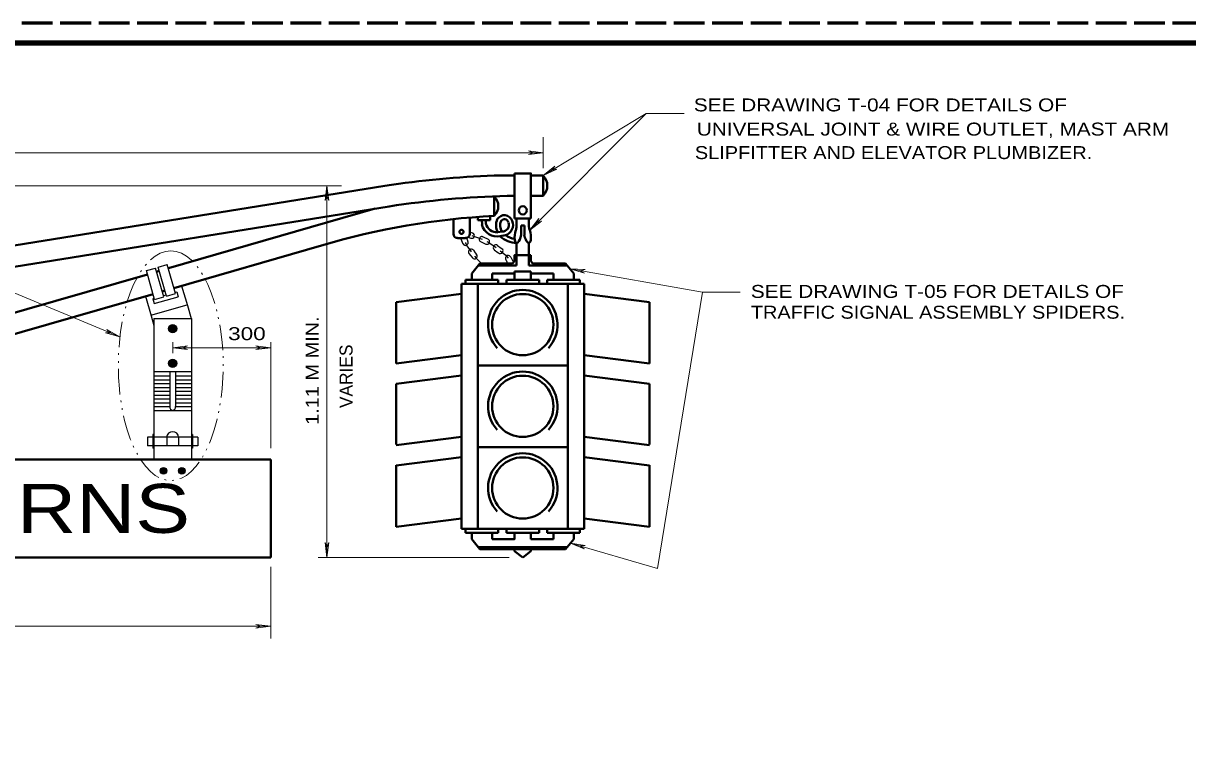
# Model space of a CAD drawing. Extents: x 312583 to 312853, y 144419 to 144586.
# Drawn here: x 312733 to 312801.3, y 144544.1 to 144586.2 of the extents above; entities that cross this region are included whole.
import ezdxf
from ezdxf.enums import TextEntityAlignment as Align

# ---------------------------------------------------------------- set-up
doc = ezdxf.new("R2010")
doc.units = 0
doc.header["$LTSCALE"] = 0.3
doc.linetypes.add('DASH_DOUBLE_DOT', pattern=[9.2, 5, -1.2, 0.3, -1.2, 0.3, -1.2])
doc.linetypes.add('LONG_DASHED', pattern=[7.5, 6, -1.5])
for name, color, linetype, lineweight in [('1', 7, 'Continuous', 40), ('2', 7, 'Continuous', 13), ('63', 7, 'LONG_DASHED', 60)]:
    doc.layers.add(name, color=color, linetype=linetype, lineweight=lineweight)

msp = doc.modelspace()

# ---------------------------------------------------------------- hatches: boundary and pattern name
at = {"layer": '1'}
for points in [[(312742.0334, 144568.3054, 1), (312741.5514, 144568.3054, 1)], [(312741.9621, 144568.3054, 1), (312741.6227, 144568.3054, 1)], [(312742.0308, 144566.2761, 1), (312741.5488, 144566.2761, 1)], [(312741.9595, 144566.2761, 1), (312741.6201, 144566.2761, 1)], [(312741.4415, 144559.9738, 1), (312741.0592, 144559.9738, 1)], [(312742.5203, 144559.9738, 1), (312742.138, 144559.9738, 1)]]:
    msp.add_hatch(color=256, dxfattribs=at).paths.add_polyline_path(points)

# ---------------------------------------------------------------- linework, layer by layer
for p, q in [((312761.8484, 144577.2983), (312760.6524, 144577.2983)), ((312761.8484, 144574.7759), (312761.8484, 144577.4133)), ((312763.5274, 144577.2983), (312762.8068, 144577.2983)), ((312763.5274, 144577.2983), (312763.5274, 144576.1253)), ((312699.5568, 144567.8759), (312754.2354, 144576.6849)), ((312760.6524, 144576.0716), (312760.6524, 144574.9216)), ((312761.8484, 144576.1023), (312761.4191, 144576.1023)), ((312763.5274, 144576.1023), (312762.8068, 144576.1023)), ((312699.5568, 144566.6493), (312754.4884, 144575.4813)), ((312741.5366, 144571.8488), (312753.6758, 144575.3509)), ((312758.2604, 144574.7376), (312758.2604, 144573.8713)), ((312759.2188, 144574.8296), (312759.2188, 144573.8713)), ((312759.6941, 144574.8679), (312759.6941, 144574.6686)), ((312760.4148, 144574.6686), (312759.6941, 144574.6686)), ((312759.9318, 144574.6686), (312759.9394, 144574.4156)), ((312760.1694, 144574.6686), (312760.1694, 144574.4769)), ((312760.4148, 144574.9139), (312760.4148, 144574.6686)), ((312762.8068, 144574.7759), (312761.8484, 144574.7759)), ((312761.9711, 144574.2853), (312761.9711, 144574.7759)), ((312762.6918, 144574.2853), (312762.6918, 144574.7759)), ((312762.6918, 144574.2853), (312762.6918, 144574.7759)), ((312761.1201, 144574.0016), (312760.8594, 144573.9633)), ((312761.0128, 144573.7409), (312761.3118, 144573.7946)), ((312762.4234, 144574.3696), (312762.2394, 144574.3696)), ((312762.2394, 144573.8099), (312762.2394, 144574.3696)), ((312762.4234, 144573.8099), (312762.4234, 144574.3696)), ((312741.8649, 144570.6936), (312750.5248, 144573.1966)), ((312758.9734, 144573.6259), (312758.4981, 144573.6259)), ((312761.9711, 144572.6216), (312761.9711, 144573.3346)), ((312762.6918, 144572.6216), (312762.6918, 144573.3499)), ((312761.8484, 144572.2613), (312761.8484, 144572.6216)), ((312761.9711, 144572.0236), (312761.9711, 144572.6216)), ((312762.6918, 144572.0236), (312762.6918, 144572.6216)), ((312762.8068, 144572.2613), (312762.8068, 144572.6216)), ((312759.8168, 144572.1386), (312759.3338, 144571.5406)), ((312759.7171, 144572.0236), (312761.9711, 144572.0236)), ((312761.7334, 144572.1386), (312759.8168, 144572.1386)), ((312761.8484, 144572.2613), (312761.7334, 144572.1386)), ((312762.6918, 144572.0236), (312764.9381, 144572.0236)), ((312762.8068, 144572.2613), (312762.9294, 144572.1386)), ((312764.8461, 144572.1386), (312762.9294, 144572.1386)), ((312764.8461, 144572.1386), (312765.3214, 144571.5406)), ((312718.5807, 144565.2268), (312740.3144, 144571.4967)), ((312740.8436, 144571.6493), (312740.9991, 144571.6942)), ((312760.8901, 144571.1803), (312758.9734, 144571.1803)), ((312758.9734, 144570.9426), (312758.9734, 144571.1803)), ((312759.3338, 144571.1803), (312759.3338, 144571.5406)), ((312761.8484, 144571.5406), (312760.5298, 144571.5406)), ((312760.5298, 144571.1803), (312760.5298, 144571.5406)), ((312760.8901, 144570.9426), (312760.8901, 144571.1803)), ((312763.2898, 144571.1803), (312761.3731, 144571.1803)), ((312761.3731, 144570.9426), (312761.3731, 144571.1803)), ((312762.8068, 144571.6633), (312761.8484, 144571.6633)), ((312761.8484, 144571.1803), (312761.8484, 144571.6633)), ((312762.8068, 144571.1803), (312762.8068, 144571.6633)), ((312762.8068, 144571.5406), (312764.1254, 144571.5406)), ((312763.2898, 144570.9426), (312763.2898, 144571.1803)), ((312763.7651, 144571.1803), (312765.6818, 144571.1803)), ((312763.7651, 144570.9426), (312763.7651, 144571.1803)), ((312764.1254, 144571.1803), (312764.1254, 144571.5406)), ((312765.3214, 144571.1803), (312765.3214, 144571.5406)), ((312765.6818, 144570.9426), (312765.6818, 144571.1803)), ((312741.1852, 144570.4982), (312741.329, 144570.5397)), ((312765.9271, 144570.9426), (312758.7358, 144570.9426)), ((312758.7358, 144556.5676), (312758.7358, 144570.9426)), ((312759.6941, 144556.5676), (312759.6941, 144570.9426)), ((312764.9688, 144556.5676), (312764.9688, 144570.9426)), ((312765.9271, 144556.5676), (312765.9271, 144570.9426)), ((312718.9106, 144564.0723), (312740.6426, 144570.3417)), ((312758.7358, 144570.3446), (312754.9024, 144569.8616)), ((312754.9024, 144566.2736), (312754.9024, 144569.8616)), ((312765.9271, 144570.3446), (312769.7604, 144569.8616)), ((312769.7604, 144566.2736), (312769.7604, 144569.8616)), ((312758.7358, 144566.7489), (312754.9024, 144566.2736)), ((312765.9271, 144566.7489), (312769.7604, 144566.2736)), ((312759.6941, 144566.1509), (312764.9688, 144566.1509)), ((312758.7358, 144565.5529), (312754.9024, 144565.0699)), ((312754.9024, 144561.5049), (312754.9024, 144565.0699)), ((312765.9271, 144565.5529), (312769.7604, 144565.0699)), ((312769.7604, 144561.5049), (312769.7604, 144565.0699)), ((312758.7358, 144561.9573), (312754.9024, 144561.4819)), ((312765.9271, 144561.9573), (312769.7604, 144561.4819)), ((312759.6941, 144561.3593), (312764.9688, 144561.3593)), ((312747.5424, 144560.6386), (312712.9734, 144560.6386)), ((312747.5424, 144560.6386), (312747.5424, 144554.8886)), ((312758.7358, 144560.7613), (312754.9024, 144560.2783)), ((312754.9024, 144556.6903), (312754.9024, 144560.3089)), ((312765.9271, 144560.7613), (312769.7604, 144560.2783)), ((312769.7604, 144556.6903), (312769.7604, 144560.3089)), ((312758.7358, 144557.1656), (312754.9024, 144556.6903)), ((312765.9271, 144557.1656), (312769.7604, 144556.6903)), ((312765.9271, 144556.5676), (312758.7358, 144556.5676)), ((312758.9734, 144556.5676), (312758.9734, 144556.3299)), ((312760.8901, 144556.3299), (312758.9734, 144556.3299)), ((312759.3338, 144556.3299), (312759.3338, 144555.9696)), ((312760.5298, 144556.3299), (312760.5298, 144555.9696)), ((312760.8901, 144556.5676), (312760.8901, 144556.3299)), ((312761.3731, 144556.5676), (312761.3731, 144556.3299)), ((312763.2898, 144556.3299), (312761.3731, 144556.3299)), ((312762.8068, 144556.3299), (312762.8068, 144555.9696)), ((312763.2898, 144556.5676), (312763.2898, 144556.3299)), ((312763.7651, 144556.5676), (312763.7651, 144556.3299)), ((312763.7651, 144556.3299), (312765.6818, 144556.3299)), ((312764.1254, 144556.3299), (312764.1254, 144555.9696)), ((312765.3214, 144556.3299), (312765.3214, 144555.9696)), ((312765.6818, 144556.5676), (312765.6818, 144556.3299)), ((312759.8168, 144555.3716), (312759.3338, 144555.9696)), ((312759.7171, 144555.4866), (312764.9381, 144555.4866)), ((312764.8461, 144555.3716), (312759.8168, 144555.3716)), ((312761.8484, 144555.3716), (312761.8484, 144555.2489)), ((312762.8068, 144555.9696), (312764.1254, 144555.9696)), ((312762.8068, 144555.3716), (312762.8068, 144555.2489)), ((312764.8461, 144555.3716), (312765.3214, 144555.9696)), ((312747.5424, 144554.8886), (312712.9734, 144554.8886)), ((312762.3314, 144554.8886), (312761.8484, 144555.2489)), ((312762.3314, 144554.8886), (312762.8068, 144555.2489))]:
    msp.add_line(p, q, dxfattribs=at)
at = {"layer": '1', "lineweight": 25}
for p, q in [((312759.2188, 144573.9863), (312759.3951, 144573.9173)), ((312759.0194, 144573.6336), (312759.1114, 144573.4189)), ((312759.1191, 144573.6796), (312759.2801, 144573.6183)), ((312759.3338, 144573.7716), (312759.9394, 144573.5569)), ((312740.2528, 144571.7134), (312740.7806, 144571.8616)), ((312741.2807, 144570.1762), (312740.7806, 144571.8616)), ((312740.938, 144571.9079), (312741.4751, 144572.0653)), ((312741.4196, 144570.2225), (312740.938, 144571.9079)), ((312741.9567, 144570.3706), (312741.4751, 144572.0653)), ((312740.7343, 144570.0188), (312740.2528, 144571.7134)), ((312741.4196, 144570.2225), (312741.9567, 144570.3706)), ((312741.9356, 144570.4449), (312742.0308, 144570.4725)), ((312742.0308, 144570.4725), (312742.1141, 144570.1854)), ((312742.3178, 144570.8245), (312742.6512, 144569.6669)), ((312740.1972, 144570.2132), (312740.5306, 144569.0557)), ((312740.5162, 144569.1056), (312742.6368, 144569.7168)), ((312740.6256, 144570.0658), (312740.7137, 144570.0913)), ((312740.6256, 144570.0658), (312740.7065, 144569.778)), ((312740.7065, 144569.778), (312742.1141, 144570.1854)), ((312740.7343, 144570.0188), (312741.2807, 144570.1762)), ((312741.2591, 144570.2491), (312741.4003, 144570.29)), ((312740.5306, 144569.0557), (312740.695, 144568.492)), ((312742.6512, 144569.6669), (312742.8666, 144568.9128)), ((312740.695, 144568.9128), (312742.8897, 144568.9128)), ((312740.695, 144568.9128), (312740.695, 144560.6386)), ((312742.8897, 144568.9128), (312742.8897, 144560.6386)), ((312740.695, 144565.7966), (312742.8897, 144565.7966)), ((312741.621, 144565.7966), (312741.621, 144563.7408)), ((312741.9544, 144565.7966), (312741.9544, 144563.7408)), ((312740.695, 144565.5373), (312741.621, 144565.5373)), ((312740.695, 144565.3151), (312741.621, 144565.3151)), ((312740.695, 144565.0928), (312741.621, 144565.0928)), ((312741.9544, 144565.5373), (312742.8897, 144565.5373)), ((312741.9544, 144565.3151), (312742.8897, 144565.3151)), ((312741.9544, 144565.0928), (312742.8897, 144565.0928)), ((312740.695, 144564.8613), (312741.621, 144564.8613)), ((312740.695, 144564.6391), (312741.621, 144564.6391)), ((312740.695, 144564.4168), (312741.621, 144564.4168)), ((312741.9544, 144564.8613), (312742.8897, 144564.8613)), ((312741.9544, 144564.6391), (312742.8897, 144564.6391)), ((312741.9544, 144564.4168), (312742.8897, 144564.4168)), ((312740.695, 144564.1853), (312741.621, 144564.1853)), ((312740.695, 144563.9631), (312741.621, 144563.9631)), ((312740.695, 144563.7408), (312741.621, 144563.7408)), ((312741.9544, 144564.1853), (312742.8897, 144564.1853)), ((312741.9544, 144563.9631), (312742.8897, 144563.9631)), ((312741.9544, 144563.7408), (312742.8897, 144563.7408)), ((312740.695, 144563.5093), (312742.8897, 144563.5093)), ((312740.3153, 144561.9351), (312740.3153, 144561.4443)), ((312740.6209, 144561.9351), (312740.3153, 144561.9351)), ((312740.6209, 144562.0925), (312740.6209, 144561.2961)), ((312740.695, 144562.0925), (312740.6209, 144562.0925)), ((312742.8897, 144561.9351), (312740.695, 144561.9351)), ((312741.4451, 144561.9351), (312741.4451, 144561.4443)), ((312742.1396, 144561.9351), (312742.1396, 144561.4443)), ((312742.9638, 144562.0925), (312742.8897, 144562.0925)), ((312742.9638, 144562.0925), (312742.9638, 144561.2961)), ((312743.2694, 144561.9351), (312742.9638, 144561.9351)), ((312743.2694, 144561.9351), (312743.2694, 144561.4443)), ((312740.6209, 144561.4443), (312740.3153, 144561.4443)), ((312740.695, 144561.2961), (312740.6209, 144561.2961)), ((312742.8897, 144561.4443), (312740.695, 144561.4443)), ((312742.9638, 144561.2961), (312742.8897, 144561.2961)), ((312743.2694, 144561.4443), (312742.9638, 144561.4443))]:
    msp.add_line(p, q, dxfattribs=at)
at = {"layer": '1', "lineweight": 158}
msp.add_lwpolyline([(312616.5, 144423.1446), (312616.5, 144585.0846), (312849, 144585.0846)], dxfattribs=at)
at = {"layer": '1'}
for points in [[(312762.8068, 144574.7759), (312762.8068, 144577.4133), (312761.8484, 144577.4133)], [(312762.8068, 144572.6216), (312761.8484, 144572.6216), (312762.8068, 144572.6216)], [(312761.8484, 144556.3299), (312761.8484, 144555.9696), (312760.5298, 144555.9696)]]:
    msp.add_lwpolyline(points, dxfattribs=at)
at = {"layer": '1', "lineweight": 25}
for points in [[(312758.6898, 144573.6029), (312758.6974, 144573.5876), (312758.8201, 144573.2809)], [(312758.9658, 144573.3576), (312758.9734, 144573.3346), (312759.0961, 144573.1123), (312759.2341, 144572.9053), (312759.3031, 144572.8133)], [(312759.8858, 144573.4036), (312759.8934, 144573.3959), (312760.1618, 144573.2733)], [(312759.9931, 144573.7026), (312760.0161, 144573.6949), (312760.2921, 144573.5646)], [(312760.2308, 144573.4189), (312760.4071, 144573.3346), (312760.7598, 144573.0663)], [(312760.8518, 144573.1966), (312761.0664, 144573.0356), (312761.1124, 144572.9973)], [(312759.1728, 144572.7213), (312759.2801, 144572.5756), (312759.3721, 144572.4606)], [(312759.4334, 144572.9053), (312759.5331, 144572.7673), (312759.6174, 144572.6599)], [(312759.4948, 144572.5603), (312759.5944, 144572.4453), (312759.6864, 144572.3456), (312759.8398, 144572.2153), (312759.9471, 144572.1386)], [(312760.6601, 144572.9436), (312760.8748, 144572.7826), (312760.9131, 144572.7519)], [(312761.0128, 144572.8746), (312761.3271, 144572.6293), (312761.4728, 144572.4376)], [(312761.5954, 144572.5373), (312761.6261, 144572.4989), (312761.7794, 144572.1846)], [(312761.3424, 144572.3379), (312761.3501, 144572.3303), (312761.4421, 144572.1386)]]:
    msp.add_lwpolyline(points, dxfattribs=at)
at = {"layer": '1'}
for centre, radius in [((312762.33, 144575.2541), 0.2396), ((312758.7362, 144573.9882), 0.1198), ((312762.33, 144568.5458), 1.7969), ((312762.33, 144563.7541), 1.7969), ((312762.33, 144558.9625), 1.7969)]:
    msp.add_circle(centre, radius, dxfattribs=at)
at = {"layer": '1', "lineweight": 25}
for centre, radius in [((312741.7924, 144568.3054), 0.241), ((312741.7924, 144568.3054), 0.1697), ((312741.7898, 144566.2761), 0.241), ((312741.7898, 144566.2761), 0.1697), ((312741.2504, 144559.9738), 0.1911), ((312742.3292, 144559.9738), 0.1911)]:
    msp.add_circle(centre, radius, dxfattribs=at)
at = {"layer": '1'}
for centre, radius, start, end in [((312762.9252, 144519.8457), 57.5, 92.26498, 98.69127), ((312762.8978, 144576.7012), 0.8697, 316.42875, 43.57125), ((312762.9271, 144520.2995), 55.8229, 91.54908, 98.69123), ((312760.0869, 144575.4968), 0.806, 314.6086, 45.3914), ((312762.8277, 144531.6439), 43.3337, 92.87671, 106.4991), ((312760.8237, 144574.6332), 0.6743, 193.64871, 273.00151), ((312761.6827, 144574.371), 0.9206, 157.02326, 206.52483), ((312761.2509, 144574.4861), 0.4824, 17.33553, 149.56479), ((312761.6827, 144574.371), 0.6811, 157.00611, 212.48195), ((312761.2509, 144574.4861), 0.2428, 17.33553, 149.56479), ((312761.1286, 144574.3938), 0.3891, 268.34899, 22.04299), ((312761.1286, 144574.3938), 0.6287, 286.80498, 22.04299), ((312758.4967, 144573.8684), 0.2396, 180, 270), ((312758.9758, 144573.8684), 0.2396, 270, 0), ((312760.8237, 144574.6332), 0.9138, 193.64871, 281.97007), ((312761.9269, 144574.5949), 1.0122, 232.48654, 265.6903), ((312760.9745, 144574.4162), 1.0043, 340.68381, 352.70057), ((312763.6855, 144574.4162), 1.0043, 187.29943, 199.31619), ((312761.9269, 144574.5949), 1.2518, 223.12306, 271.78295), ((312762.33, 144568.5458), 2.0365, 317.48872, 222.69673), ((312762.33, 144563.7541), 2.0365, 317.48872, 222.69673), ((312762.33, 144558.9625), 2.0365, 317.48872, 222.69673)]:
    msp.add_arc(centre, radius, start, end, dxfattribs=at)
at = {"layer": '1', "lineweight": 25}
for centre, radius, start, end in [((312759.3369, 144573.7706), 0.1597, 250.0911, 70.0911), ((312758.8419, 144573.6516), 0.1597, 188.19055, 198.42777), ((312758.9635, 144573.356), 0.1597, 209.38072, 29.38072), ((312759.9376, 144573.5531), 0.1597, 70.0911, 250.0911), ((312760.2272, 144573.4184), 0.1597, 244.76089, 64.76089), ((312760.7582, 144573.0683), 0.1597, 52.92074, 232.92074), ((312759.303, 144572.8155), 0.1597, 35.73859, 215.73859), ((312759.4959, 144572.5611), 0.1597, 219.04344, 39.04344), ((312761.0124, 144572.875), 0.1597, 231.82899, 51.82899), ((312761.4712, 144572.4372), 0.1597, 37.38145, 217.38145), ((312741.8288, 144563.7224), 0.2096, 174.74074, 259.26749), ((312741.7508, 144563.7224), 0.2096, 280.73251, 5.25926), ((312741.7898, 144561.9104), 0.3533, 5.25702, 174.74298)]:
    msp.add_arc(centre, radius, start, end, dxfattribs=at)
at = {"layer": '1'}
for centre, major_axis, start_param, end_param in [((312762.0543, 144573.8443), (0.0883, 0.5005), 1.1385722, 4.7124639), ((312762.6057, 144573.8443), (0.0883, -0.5005), 4.7123141, 8.2862057)]:
    msp.add_ellipse(centre, major_axis=major_axis, ratio=0.372027, start_param=start_param, end_param=end_param, dxfattribs=at)
at = {"layer": '1', "linetype": 'DASH_DOUBLE_DOT', "lineweight": 13}
msp.add_ellipse((312741.6786, 144566.1351), major_axis=(0, 6.7342), ratio=0.457136, dxfattribs=at)
at = {"layer": '2'}
for p, q in [((312769.5611, 144580.9246), (312762.7378, 144574.0859)), ((312763.5274, 144577.7276), (312763.5274, 144579.5523)), ((312763.5274, 144578.6323), (312649.0104, 144578.6323)), ((312762.6611, 144578.7396), (312762.9371, 144578.6323)), ((312763.5274, 144578.6323), (312762.6611, 144578.7396)), ((312762.6611, 144578.5249), (312762.9371, 144578.6323)), ((312763.5274, 144578.6323), (312762.6611, 144578.5249)), ((312763.5274, 144577.2983), (312764.2174, 144577.8426)), ((312763.5274, 144577.2983), (312764.3248, 144577.6586)), ((312764.2174, 144577.8426), (312764.0334, 144577.6049)), ((312764.3248, 144577.6586), (312764.0334, 144577.6049)), ((312751.6901, 144576.6926), (312669.5878, 144576.6926)), ((312750.8391, 144576.6926), (312750.7318, 144575.8263)), ((312750.8391, 144554.8886), (312750.8391, 144576.6926)), ((312750.8391, 144576.6926), (312750.9464, 144575.8263)), ((312750.7318, 144575.8263), (312750.8391, 144576.1023)), ((312750.9464, 144575.8263), (312750.8391, 144576.1023)), ((312721.9663, 144574.7864), (312738.6993, 144567.8305)), ((312762.7378, 144574.0859), (312763.2744, 144574.7759)), ((312762.7378, 144574.0859), (312763.4278, 144574.6226)), ((312763.2744, 144574.7759), (312763.1518, 144574.4999)), ((312763.4278, 144574.6226), (312763.1518, 144574.4999)), ((312772.8654, 144570.4443), (312765.1068, 144571.8166)), ((312765.1068, 144571.8166), (312765.9424, 144571.5559)), ((312765.1068, 144571.8166), (312765.9808, 144571.7706)), ((312765.9808, 144571.7706), (312765.6894, 144571.7093)), ((312765.9424, 144571.5559), (312765.6894, 144571.7093)), ((312737.8566, 144568.0658), (312738.1494, 144568.0581)), ((312738.6993, 144567.8305), (312737.8566, 144568.0658)), ((312737.9369, 144568.264), (312738.1494, 144568.0581)), ((312738.6993, 144567.8305), (312737.9369, 144568.264)), ((312741.7924, 144566.8692), (312741.7924, 144567.5089)), ((312741.7924, 144567.1891), (312742.6588, 144567.2964)), ((312747.5424, 144567.1891), (312741.7924, 144567.1891)), ((312741.7924, 144567.1891), (312742.6588, 144567.0817)), ((312742.6588, 144567.2964), (312742.3828, 144567.1891)), ((312742.6588, 144567.0817), (312742.3828, 144567.1891)), ((312746.6761, 144567.2964), (312746.9521, 144567.1891)), ((312747.5424, 144567.1891), (312746.6761, 144567.2964)), ((312746.6761, 144567.0817), (312746.9521, 144567.1891)), ((312747.5424, 144567.1891), (312746.6761, 144567.0817)), ((312747.5424, 144561.3056), (312747.5424, 144567.5089)), ((312750.7318, 144555.7549), (312750.8391, 144555.4789)), ((312750.8391, 144554.8886), (312750.7318, 144555.7549)), ((312750.9464, 144555.7549), (312750.8391, 144555.4789)), ((312750.8391, 144554.8886), (312750.9464, 144555.7549)), ((312765.1374, 144555.7319), (312765.9348, 144555.3869)), ((312765.1374, 144555.7319), (312765.9961, 144555.5939)), ((312765.9961, 144555.5939), (312765.7048, 144555.5633)), ((312765.9348, 144555.3869), (312765.7048, 144555.5633)), ((312761.5341, 144554.8886), (312750.3178, 144554.8886)), ((312747.5424, 144550.1353), (312747.5424, 144554.3366)), ((312747.5424, 144550.8483), (312712.9734, 144550.8483)), ((312746.6761, 144550.9556), (312746.9521, 144550.8483)), ((312747.5424, 144550.8483), (312746.6761, 144550.9556)), ((312746.6761, 144550.7409), (312746.9521, 144550.8483)), ((312747.5424, 144550.8483), (312746.6761, 144550.7409))]:
    msp.add_line(p, q, dxfattribs=at)
for points in [[(312771.7921, 144580.9246), (312769.5611, 144580.9246), (312763.5274, 144577.2983)], [(312775.0888, 144570.4443), (312772.8654, 144570.4443), (312770.2434, 144554.2446), (312765.1374, 144555.7319)]]:
    msp.add_lwpolyline(points, dxfattribs=at)
at = {"layer": '63'}
msp.add_line((312851.75, 144586.2246), (312583.526, 144586.2246), dxfattribs=at)

# ---------------------------------------------------------------- texts
at = {"layer": '1', "width": 1.25}
msp.add_text('NO TURNS', height=2.875, dxfattribs=at).set_placement((312730.2579, 144556.3299), align=Align.CENTER)
at = {"layer": '2'}
for s, width, p in [('SEE DRAWING T-04 FOR DETAILS OF', 1.2, (312772.3659, 144581.0558)), ('UNIVERSAL JOINT & WIRE OUTLET, MAST ARM', 1.2, (312772.5389, 144579.6376)), ('SLIPFITTER AND ELEVATOR PLUMBIZER.', 1.15, (312772.4253, 144578.2576)), ('SEE DRAWING T-05 FOR DETAILS OF', 1.2, (312775.7098, 144570.1136)), ('TRAFFIC SIGNAL ASSEMBLY SPIDERS.', 1.15, (312775.7098, 144568.8936)), ('300 ', 1.3, (312745.044, 144567.6362))]:
    msp.add_text(s, height=0.76, dxfattribs=dict(at, width=width)).set_placement(p)
at = {"layer": '2', "width": 1.15}
msp.add_text('1.11 M MIN.', height=0.76, rotation=90, dxfattribs=at).set_placement((312750.3596, 144562.664))
at = {"layer": '2'}
msp.add_text('VARIES', height=0.76, rotation=90, dxfattribs=at).set_placement((312752.3426, 144563.6518))

doc.saveas('drawing.dxf')
